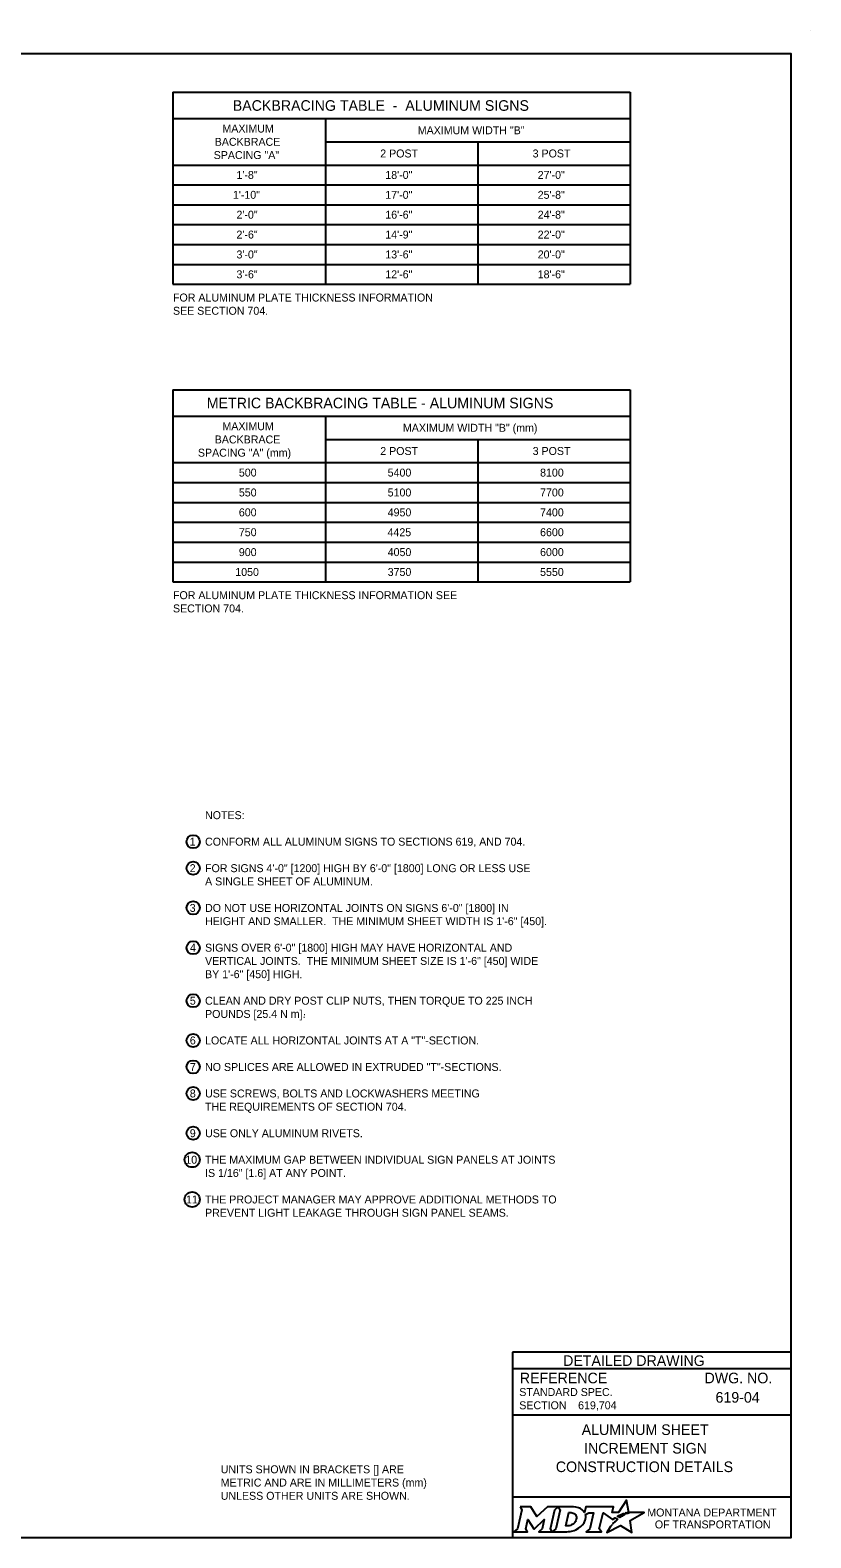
# Model space of a CAD drawing. Extents: x 49991.4 to 50021, y 49987.6 to 50011.4.
# Drawn here: x 50011.01 to 50016.9, y 49987.8 to 49999.18 of the extents above; entities that cross this region are included whole.
import ezdxf

# ---------------------------------------------------------------- set-up
doc = ezdxf.new("R2010")
doc.units = 0
for name, color, linetype in [('Default', 7, 'Continuous'), ('Level 1', 7, 'Continuous'), ('Level 2', 7, 'Continuous'), ('Level 5', 7, 'Continuous')]:
    doc.layers.add(name, color=color, linetype=linetype)

msp = doc.modelspace()

# ---------------------------------------------------------------- linework, layer by layer
at = {"layer": 'Default'}
for points in [[(50015.513, 49987.981), (50015.502, 49987.987), (50015.514, 49987.99), (50015.526, 49987.991), (50015.508, 49988.082), (50015.449, 49987.99), (50015.401, 49987.99), (50015.412, 49988.034), (50015.202, 49988.034), (50015.192, 49987.991), (50015.186, 49988)], [(50014.706, 49988.034), (50014.72, 49988.01), (50014.686, 49987.867), (50014.66, 49987.845), (50014.762, 49987.845), (50014.749, 49987.867), (50014.765, 49987.937), (50014.809, 49987.868), (50014.814, 49987.868), (50014.889, 49987.938), (50014.872, 49987.867), (50014.848, 49987.845), (50014.949, 49987.845), (50014.936, 49987.868), (50014.969, 49988.011)], [(50014.969, 49988.011), (50014.994, 49988.034), (50014.912, 49988.034), (50014.832, 49987.961), (50014.788, 49988.034), (50014.706, 49988.034)], [(50015.108, 49988.034), (50014.994, 49988.034), (50015.009, 49988.011), (50014.975, 49987.867), (50014.949, 49987.845), (50015.06, 49987.845)], [(50015.132, 49987.947), (50015.13, 49987.939), (50015.127, 49987.93), (50015.123, 49987.922), (50015.118, 49987.914), (50015.111, 49987.907), (50015.103, 49987.901), (50015.095, 49987.896), (50015.086, 49987.892), (50015.077, 49987.89), (50015.067, 49987.889), (50015.052, 49987.889), (50015.075, 49987.989), (50015.091, 49987.989), (50015.099, 49987.988), (50015.106, 49987.986), (50015.113, 49987.983), (50015.119, 49987.979), (50015.124, 49987.974), (50015.128, 49987.968), (50015.13, 49987.962), (50015.132, 49987.955), (50015.132, 49987.952), (50015.132, 49987.947)], [(50015.199, 49987.975), (50015.224, 49987.988), (50015.261, 49987.988), (50015.232, 49987.867), (50015.205, 49987.845), (50015.321, 49987.845), (50015.304, 49987.867), (50015.332, 49987.988), (50015.403, 49987.936), (50015.424, 49987.951), (50015.444, 49987.94)], [(50015.388, 49987.884), (50015.373, 49987.86), (50015.368, 49987.852), (50015.362, 49987.844), (50015.36, 49987.839), (50015.465, 49987.893), (50015.549, 49987.838), (50015.536, 49987.93), (50015.643, 49987.989), (50015.594, 49987.989), (50015.564, 49987.99), (50015.543, 49987.99), (50015.536, 49987.989), (50015.531, 49987.987), (50015.523, 49987.985), (50015.513, 49987.981)], [(50015.462, 49987.954), (50015.46, 49987.952), (50015.442, 49987.961), (50015.452, 49987.967), (50015.456, 49987.969), (50015.465, 49987.973), (50015.47, 49987.976), (50015.478, 49987.979), (50015.485, 49987.982), (50015.497, 49987.974), (50015.493, 49987.972), (50015.489, 49987.97), (50015.484, 49987.967), (50015.479, 49987.965), (50015.478, 49987.963), (50015.475, 49987.962), (50015.472, 49987.96), (50015.47, 49987.959), (50015.467, 49987.957), (50015.465, 49987.955), (50015.462, 49987.954)], [(50015.106, 49987.852), (50015.114, 49987.855), (50015.127, 49987.86), (50015.148, 49987.871)], [(50015.402, 49987.9), (50015.402, 49987.9)]]:
    msp.add_lwpolyline(points, dxfattribs=at)
for centre, radius, start, end in [((50015.087, 49987.973), 0.118, 300.9103, 339.1383), ((50015.131, 49987.955), 0.0709, 339.5329, 15.8582)]:
    msp.add_arc(centre, radius, start, end, dxfattribs=at)
for centre, major_axis, ratio, start_param, end_param in [((50015.106, 49987.986), (0.0834, -0.0037), 0.568097, 0.61298, 1.570796), ((50015.161, 49987.994), (0.0361, -0.0295), 0.469099, 1.225588, 1.570796), ((50015.433, 49987.93), (-0.0112, -0.0097), 0.021651, 3.157348, 6.283185), ((50015.06, 49987.993), (0, 0.148), 0.987302, 3.139398, 3.456847), ((50015.395, 49987.892), (-0.00694, -0.00806), 0.008222, 0, 3.137361), ((50015.412, 49987.911), (-0.0098, -0.0102), 0.016458, 3.141593, 6.279097)]:
    msp.add_ellipse(centre, major_axis=major_axis, ratio=ratio, start_param=start_param, end_param=end_param, dxfattribs=at)
at = {"layer": 'Level 1'}
msp.add_line((50016.9, 49999.176), (50016.9, 49999.176), dxfattribs=at)
msp.add_lwpolyline([(49999.384, 49998.999), (50016.75, 49998.999), (50016.75, 49987.799), (49999.384, 49987.799)], close=True, dxfattribs=at)
at = {"layer": 'Level 2'}
for p, q in [((50012.087, 49998.708), (50015.537, 49998.708)), ((50012.087, 49998.708), (50012.087, 49997.258)), ((50015.537, 49998.708), (50015.537, 49997.258)), ((50012.087, 49998.508), (50015.537, 49998.508)), ((50013.237, 49998.508), (50013.237, 49997.258)), ((50013.237, 49998.333), (50015.537, 49998.333)), ((50014.387, 49998.333), (50014.387, 49997.258)), ((50012.087, 49998.158), (50015.537, 49998.158)), ((50012.087, 49998.008), (50015.537, 49998.008)), ((50012.087, 49997.858), (50015.537, 49997.858)), ((50012.087, 49997.708), (50015.537, 49997.708)), ((50012.087, 49997.558), (50015.537, 49997.558)), ((50012.087, 49997.408), (50015.537, 49997.408)), ((50012.087, 49997.258), (50015.537, 49997.258)), ((50012.087, 49996.462), (50015.537, 49996.462)), ((50012.087, 49996.462), (50012.087, 49995.012)), ((50015.537, 49996.462), (50015.537, 49995.012)), ((50012.087, 49996.262), (50015.537, 49996.262)), ((50013.237, 49996.262), (50013.237, 49995.012)), ((50013.237, 49996.087), (50015.537, 49996.087)), ((50014.387, 49996.087), (50014.387, 49995.012)), ((50012.087, 49995.912), (50015.537, 49995.912)), ((50012.087, 49995.762), (50015.537, 49995.762)), ((50012.087, 49995.612), (50015.537, 49995.612)), ((50012.087, 49995.462), (50015.537, 49995.462)), ((50012.087, 49995.312), (50015.537, 49995.312)), ((50012.087, 49995.162), (50015.537, 49995.162)), ((50012.087, 49995.012), (50015.537, 49995.012))]:
    msp.add_line(p, q, dxfattribs=at)
for centre, radius in [((50012.239, 49993.052), 0.05), ((50012.239, 49992.852), 0.05), ((50012.239, 49992.552), 0.05), ((50012.239, 49992.252), 0.05), ((50012.239, 49991.852), 0.05), ((50012.239, 49991.552), 0.05), ((50012.239, 49991.352), 0.05), ((50012.239, 49991.152), 0.05), ((50012.239, 49990.852), 0.05), ((50012.232, 49990.652), 0.0569), ((50012.232, 49990.352), 0.0569)]:
    msp.add_circle(centre, radius, dxfattribs=at)
at = {"layer": 'Level 5'}
for p, q in [((50016.75, 49989.199), (50014.65, 49989.199)), ((50014.65, 49989.199), (50014.65, 49987.799)), ((50016.75, 49989.074), (50014.65, 49989.074)), ((50016.386, 49988.859), (50016.386, 49988.859)), ((50016.75, 49988.724), (50014.65, 49988.724)), ((50015.144, 49988.799), (50015.144, 49988.799)), ((50015.7, 49988.475), (50015.7, 49988.475)), ((50016.75, 49988.106), (50014.65, 49988.106))]:
    msp.add_line(p, q, dxfattribs=at)

# ---------------------------------------------------------------- texts
at = {"layer": 'Default'}
for s, p in [('MONTANA DEPARTMENT', (50015.666, 49987.96)), ('OF TRANSPORTATION', (50015.723, 49987.87))]:
    msp.add_text(s, height=0.06, rotation=360, dxfattribs=at).set_placement(p)
at = {"layer": 'Level 2'}
for s, height, p in [('BACKBRACING TABLE  -  ALUMINUM SIGNS', 0.08, (50012.538, 49998.567)), ('MAXIMUM', 0.06, (50012.46, 49998.403)), ('MAXIMUM WIDTH "B"', 0.06, (50013.934, 49998.39)), ('BACKBRACE ', 0.06, (50012.402, 49998.303)), ('SPACING "A"', 0.06, (50012.394, 49998.203)), ('2 POST', 0.06, (50013.651, 49998.215)), ('3 POST', 0.06, (50014.801, 49998.215)), ('1\'-8"', 0.06, (50012.566, 49998.053)), ('18\'-0"', 0.06, (50013.689, 49998.053)), ('27\'-0"', 0.06, (50014.839, 49998.053)), ('1\'-10"', 0.06, (50012.539, 49997.903)), ('17\'-0"', 0.06, (50013.689, 49997.903)), ('25\'-8"', 0.06, (50014.839, 49997.903)), ('2\'-0"', 0.06, (50012.566, 49997.753)), ('16\'-6"', 0.06, (50013.689, 49997.753)), ('24\'-8"', 0.06, (50014.839, 49997.753)), ('2\'-6"', 0.06, (50012.566, 49997.603)), ('14\'-9"', 0.06, (50013.689, 49997.603)), ('22\'-0"', 0.06, (50014.839, 49997.603)), ('3\'-0"', 0.06, (50012.566, 49997.453)), ('13\'-6"', 0.06, (50013.689, 49997.453)), ('20\'-0"', 0.06, (50014.839, 49997.453)), ('3\'-6"', 0.06, (50012.566, 49997.303)), ('12\'-6"', 0.06, (50013.689, 49997.303)), ('18\'-6"', 0.06, (50014.839, 49997.303)), ('FOR ALUMINUM PLATE THICKNESS INFORMATION', 0.06, (50012.087, 49997.128)), ('SEE SECTION 704.', 0.06, (50012.087, 49997.028)), ('METRIC BACKBRACING TABLE - ALUMINUM SIGNS', 0.08, (50012.342, 49996.322)), ('BACKBRACE ', 0.06, (50012.402, 49996.057)), ('MAXIMUM', 0.06, (50012.46, 49996.157)), ('MAXIMUM WIDTH "B" (mm)', 0.06, (50013.822, 49996.145)), ('SPACING "A" (mm)', 0.06, (50012.275, 49995.957)), ('2 POST', 0.06, (50013.651, 49995.97)), ('3 POST', 0.06, (50014.801, 49995.97)), ('500', 0.06, (50012.584, 49995.807)), ('5400', 0.06, (50013.707, 49995.807)), ('8100', 0.06, (50014.857, 49995.807)), ('550', 0.06, (50012.584, 49995.657)), ('5100', 0.06, (50013.707, 49995.657)), ('7700', 0.06, (50014.857, 49995.657)), ('600', 0.06, (50012.584, 49995.507)), ('4950', 0.06, (50013.707, 49995.507)), ('7400', 0.06, (50014.857, 49995.507)), ('750', 0.06, (50012.584, 49995.357)), ('4425', 0.06, (50013.706, 49995.357)), ('6600', 0.06, (50014.857, 49995.357)), ('900', 0.06, (50012.584, 49995.207)), ('4050', 0.06, (50013.707, 49995.207)), ('6000', 0.06, (50014.857, 49995.207)), ('1050', 0.06, (50012.557, 49995.057)), ('3750', 0.06, (50013.707, 49995.057)), ('5550', 0.06, (50014.857, 49995.057)), ('FOR ALUMINUM PLATE THICKNESS INFORMATION SEE', 0.06, (50012.087, 49994.882)), ('SECTION 704.', 0.06, (50012.087, 49994.782)), ('NOTES:', 0.06, (50012.329, 49993.222)), ('1', 0.06, (50012.213, 49993.022)), ('CONFORM ALL ALUMINUM SIGNS TO SECTIONS 619, AND 704.', 0.06, (50012.329, 49993.022)), ('2', 0.06, (50012.213, 49992.822)), ('FOR SIGNS 4\'-0" [1200] HIGH BY 6\'-0" [1800] LONG OR LESS USE', 0.06, (50012.329, 49992.822)), ('A SINGLE SHEET OF ALUMINUM.', 0.06, (50012.329, 49992.722)), ('3', 0.06, (50012.213, 49992.522)), ('DO NOT USE HORIZONTAL JOINTS ON SIGNS 6\'-0" [1800] IN', 0.06, (50012.329, 49992.522)), ('HEIGHT AND SMALLER.  THE MINIMUM SHEET WIDTH IS 1\'-6" [450].', 0.06, (50012.329, 49992.422)), ('4', 0.06, (50012.215, 49992.222)), ('SIGNS OVER 6\'-0" [1800] HIGH MAY HAVE HORIZONTAL AND ', 0.06, (50012.329, 49992.222)), ('VERTICAL JOINTS.  THE MINIMUM SHEET SIZE IS 1\'-6" [450] WIDE', 0.06, (50012.329, 49992.122)), ('BY 1\'-6" [450] HIGH.', 0.06, (50012.329, 49992.022)), ('5', 0.06, (50012.214, 49991.822)), ('CLEAN AND DRY POST CLIP NUTS, THEN TORQUE TO 225 INCH', 0.06, (50012.329, 49991.822)), ('POUNDS [25.4 N m].', 0.06, (50012.329, 49991.722)), ('.', 0.06, (50013.068, 49991.742)), ('6', 0.06, (50012.214, 49991.522)), ('LOCATE ALL HORIZONTAL JOINTS AT A "T"-SECTION.', 0.06, (50012.329, 49991.522)), ('7', 0.06, (50012.215, 49991.322)), ('NO SPLICES ARE ALLOWED IN EXTRUDED "T"-SECTIONS.', 0.06, (50012.329, 49991.322)), ('8', 0.06, (50012.214, 49991.122)), ('USE SCREWS, BOLTS AND LOCKWASHERS MEETING', 0.06, (50012.329, 49991.122)), ('THE REQUIREMENTS OF SECTION 704.', 0.06, (50012.329, 49991.022)), ('9', 0.06, (50012.214, 49990.822)), ('USE ONLY ALUMINUM RIVETS.', 0.06, (50012.329, 49990.822)), ('10', 0.06, (50012.18, 49990.622)), ('THE MAXIMUM GAP BETWEEN INDIVIDUAL SIGN PANELS AT JOINTS', 0.06, (50012.329, 49990.622)), ('IS 1/16" [1.6] AT ANY POINT.', 0.06, (50012.329, 49990.522)), ('11', 0.06, (50012.185, 49990.322)), ('THE PROJECT MANAGER MAY APPROVE ADDITIONAL METHODS TO', 0.06, (50012.329, 49990.322)), ('PREVENT LIGHT LEAKAGE THROUGH SIGN PANEL SEAMS.', 0.06, (50012.329, 49990.222)), ('619-04', 0.08, (50016.181, 49988.819)), ('619,704', 0.06, (50015.144, 49988.769)), ('ALUMINUM SHEET', 0.08, (50015.171, 49988.575)), ('INCREMENT SIGN', 0.08, (50015.189, 49988.435)), ('UNITS SHOWN IN BRACKETS [] ARE ', 0.06, (50012.447, 49988.286)), ('CONSTRUCTION DETAILS', 0.08, (50014.976, 49988.295)), ('METRIC AND ARE IN MILLIMETERS (mm) ', 0.06, (50012.447, 49988.186)), ('UNLESS OTHER UNITS ARE SHOWN.', 0.06, (50012.447, 49988.086))]:
    msp.add_text(s, height=height, dxfattribs=at).set_placement(p)
at = {"layer": 'Level 5'}
for s, height, p in [('DETAILED DRAWING', 0.0799, (50015.031, 49989.096)), ('REFERENCE', 0.08, (50014.704, 49988.965)), ('DWG. NO.', 0.08, (50016.098, 49988.965)), ('STANDARD SPEC.', 0.06, (50014.7, 49988.869)), ('SECTION', 0.06, (50014.7, 49988.769))]:
    msp.add_text(s, height=height, dxfattribs=at).set_placement(p)

doc.saveas('drawing.dxf')
